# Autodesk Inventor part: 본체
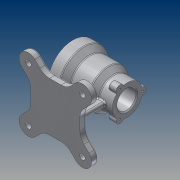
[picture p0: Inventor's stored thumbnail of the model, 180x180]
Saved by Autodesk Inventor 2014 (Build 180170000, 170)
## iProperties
Created: 2017-03
Part Number: 본체
Material: 알루미늄 6061
Document SubType Name: Modeling
Designer: Administrator
Density: 2.71 g/cm^3
Appearance: 알루미늄 - 평지
Mass: 1003.29 g
Surface Area: 840.489 cm^2
Volume: 370.217 cm^3
Author: Administrator
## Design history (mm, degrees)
sketch "스케치1"
  geometry: L1 (-50, 0)-(50, 0); L2 (-50, 45)-(-31.071, 45); L3 (-29.171, 44.322)-(-19.829, 36.678); L4 (-17.929, 36)-(13.929, 36); L5 (15.829, 35.322)-(24.56, 28.178); L6 (26.46, 27.5)-(50, 27.5); L7 (50, 27.5)-(50, 17.5); L8 (50, 17.5)-(23, 17.5); L9 (20, 20.5)-(20, 23); L10 (17, 26)-(-24, 26); L11 (-27, 29)-(-27, 32); L12 (-30, 35)-(-50, 35); L13 (-50, 35)-(-50, 45); A1 r 3 centre (-31.071, 42) between (-29.171, 44.322) and (-31.071, 45); A2 r 3 centre (-17.929, 39) between (-19.829, 36.678) and (-17.929, 36); A3 r 3 centre (13.929, 33) between (15.829, 35.322) and (13.929, 36); A4 r 3 centre (26.46, 30.5) between (24.56, 28.178) and (26.46, 27.5); A5 r 3 centre (-30, 32) between (-27, 32) and (-30, 35); A6 r 3 centre (-24, 29) between (-27, 29) and (-24, 26); A7 r 3 centre (17, 23) between (20, 23) and (17, 26); A8 r 3 centre (23, 20.5) between (20, 20.5) and (23, 17.5); 10 further points
  constraints: 26 end point, 16 point on circle, 16 point on line, 16 tangent, 10 parallel, 8 centre point, 7 equal radius, 2 vertical alignment, 1 coincident, 1 horizontal, 1 midpoint, 1 perpendicular
  dimensions: "d0" = 100 distance of L1.start L1.end; "d1" = 90 diameter of L2 L1; "d2" = 70 diameter of L12 L1; "d3" = 52 diameter of L10 L1; "d4" = 35 diameter of L8 L1; "d5" = 72 diameter of L4 L1; "d6" = 55 diameter of L6 L1; "d7" = 30 distance between parallel lines of L9 L7; "d8" = 23 distance between parallel lines of L11 L13; "d9" = 20 distance from line of point (-30, 45) L13; "d10" = 31 distance from line of point (-19, 36) L13; "d11" = 65 distance from line of L13 point (15, 36); "d13" = 3 radius of A1
revolve "회전1" sketch "스케치1" stored, may be unused: angle "d12" = 90 deg
node "작업 평면1"
sketch "스케치2"
  geometry: L1 (0, 0)-(74.496, 74.496); L2 (0, 0)-(105.353, 0); L3 (61.518, 37.477)-(52.322, 28.281); L4 (37.477, 61.518)-(28.281, 52.322); L5 (37.477, -61.518)-(28.281, -52.322); L6 (61.518, -37.477)-(52.322, -28.281); L7 (0, 0)-(0, 108.585); L8 (-37.477, 61.518)-(-28.281, 52.322); L9 (-61.518, 37.477)-(-52.322, 28.281); L10 (-61.518, -37.477)-(-52.322, -28.281); L11 (-37.477, -61.518)-(-28.281, -52.322); L12 (-10.603, 45)-(10.603, 45); L13 (-45, -10.603)-(-45, 10.603); L14 (10.603, -45)-(-10.603, -45); L15 (45, 10.603)-(45, -10.603); C1 r 5 at (49.497, 49.497); C2 r 5 at (49.497, -49.497); C3 r 5 at (-49.497, 49.497); C4 r 5 at (-49.497, -49.497); A1 r 70 centre (0, 0) between (49.497, 49.497) and (59.97, 36.106); A2 r 17 centre (49.497, 49.497) between (59.97, 36.106) and (36.106, 59.97); A3 r 17 centre (49.497, -49.497) between (36.106, -59.97) and (59.97, -36.106); A4 r 17 centre (-49.497, 49.497) between (-36.106, 59.97) and (-59.97, 36.106); A5 r 17 centre (-49.497, -49.497) between (-59.97, -36.106) and (-36.106, -59.97); A6 r 25 centre (-10.603, 70) between (-28.281, 52.322) and (-10.603, 45); A7 r 25 centre (10.603, 70) between (10.603, 45) and (28.281, 52.322); A8 r 25 centre (70, 10.603) between (52.322, 28.281) and (45, 10.603); A9 r 25 centre (70, -10.603) between (45, -10.603) and (52.322, -28.281); A10 r 25 centre (10.603, -70) between (28.281, -52.322) and (10.603, -45); A11 r 25 centre (-10.603, -70) between (-10.603, -45) and (-28.281, -52.322); A12 r 25 centre (-70, -10.603) between (-52.322, -28.281) and (-45, -10.603); A13 r 25 centre (-70, 10.603) between (-45, 10.603) and (-52.322, 28.281); 10 further points
  constraints: 35 point on circle, 30 end point, 24 symmetric about line, 17 centre point, 17 point on line, 16 tangent, 5 coincident, 5 equal radius, 2 horizontal, 2 midpoint, 2 parallel, 2 perpendicular, 1 equal length, 1 horizontal alignment, 1 vertical alignment, 6 other
  dimensions: "d17" = 45 deg angle of L2 L1; "d18" = 17 distance between parallel lines of L3 L1; "d19" = 17 distance between parallel lines of L4 L1; "d20" = 140 diameter of A1; "d21" = 10 diameter of C1; "d22" = 34 diameter of A2; "d26" = 90 distance between parallel lines of L15 L13; "d27" = 90 distance between parallel lines of L12 L14; "d30" = 25 radius of A6; "d31" = 25 radius of A10; "d32" = 25 radius of A12
extrude "돌출1" join sketch "스케치2" distance "d28" = 12; taper "d29" = 0 deg
sketch "스케치3"
  geometry: L1 (37, 4)-(-37, 4); L2 (-37, 4)-(-37, -4); L3 (-37, -4)-(37, -4); L4 (37, -4)-(37, 4); 3 further points
  constraints: 8 end point, 2 midpoint, 2 parallel, 1 horizontal, 1 horizontal alignment, 1 perpendicular, 1 vertical alignment
  dimensions: "d33" = 8 distance between parallel lines of L3 L1; "d34" = 37 distance from line of point (0, 0) L4
extrude "돌출2" join sketch "스케치3" stored distance "d35" = 12; taper "d36" = 0 deg
sketch "스케치4"
  geometry: L1 (-70, -28.281)-(-70, -37.477) reference; L2 (-70, 37.477)-(-70, 28.281) reference; L3 (-70, 25)-(-31.096, 18.14); L4 (-70, -25)-(-31.096, -18.14); A1 r 36 centre (0, 0) between (-35.777, -4) and (-35.777, 4) reference; 1 further point
  constraints: 4 end point, 2 point on circle, 2 point on line
  dimensions: "d37" = 100 deg angle of L2 L3; "d38" = 100 deg angle of L1 L4; "d39" = 25 vertical distance of L4.start point (0, 0); "d40" = 25 vertical distance of L3.start point (0, 0)
feature "리브1" dims "d41" = 1, "d42" = 8, "d43" = 0, "d44" = 0, "d45" = 1, "d46" = 1
feature "리브2" dims "d47" = 1, "d48" = 8, "d49" = 0, "d50" = 0, "d51" = 1, "d52" = 1
sketch "스케치5"
  geometry: A1 r 27.5 centre (0, 0) between (0, 27.5) and (-6.943, 26.609) reference; A2 r 7 centre (0, 27.5) between (6.943, 26.609) and (-6.943, 26.609); 1 further point
  constraints: 5 point on circle, 1 centre point, 1 vertical alignment
  dimensions: "d53" = 14 diameter of A2
extrude "돌출3" join sketch "스케치5" distance "d54" = 15; taper "d55" = 0 deg
sketch "스케치6"
  geometry: A1 r 7 centre (0, 0) between (6.943, -0.891) and (-6.943, -0.891) reference; 1 further point
hole "구멍1" sketch "스케치6" at (0, 0) diameter "d56" = 3.242; stored, may be unused: countersink angle "d60" = 90 deg, drill point angle "d62" = 118 deg; dims "d57" = 9, "d58" = 4, "d59" = 2, "d61" = 11
node "작업 평면2"
sketch "스케치7"
  geometry: C1 r 5 at (0, 0); 1 further point
  constraints: 1 centre point, 1 coincident
  dimensions: "d67" = 10 diameter of C1
extrude "돌출4" join sketch "스케치7" stored distance "d68" = 15; taper "d69" = 0 deg
hole "구멍2" diameter "d72" = 4.134; stored, may be unused: countersink angle "d76" = 90 deg, drill point angle "d78" = 118 deg; dims "d70" = 10, "d71" = 10, "d73" = 9, "d74" = 4, "d75" = 2, "d77" = 11
chamfer "모따기1" distance "d79" = 2; stored, may be unused: second distance "d80" = 2, angle "d81" = 45 deg
fillet "모깎기3" dims "d84" = 3
fillet "모깎기4" dims "d85" = 1
fillet "모깎기5" dims "d86" = 3
fillet "모깎기6" dims "d87" = 3
fillet "모깎기7" dims "d88" = 3
sketch "스케치8"
  geometry: 2 further points
  constraints: 1 vertical alignment
  dimensions: "d89" = 40 distance of point (0, 0) point (0, 40)
hole "구멍3" sketch "스케치8" at (0, 40) diameter "d90" = 3.242; stored, may be unused: countersink angle "d94" = 90 deg, drill point angle "d96" = 118 deg; dims "d91" = 9, "d92" = 4, "d93" = 2, "d95" = 11
sketch "스케치9"
  geometry: 2 further points
  constraints: 1 vertical alignment, 1 other
  dimensions: "d100" = 35 distance of point (0, -35) point (0, 0)
feature "엠보싱1" sketch "스케치9" dims "d0" = 100, "d1" = 90, "d2" = 70, "d3" = 52, "d4" = 35, "d5" = 72, "d6" = 55, "d7" = 30, "d8" = 23, "d9" = 20, "d10" = 31, "d11" = 65, "d13" = 3, "d101" = 0.5, "d102" = 0
node "솔리드1"
pattern_circular "원형 패턴1" dims angle "d64" = 360 deg
pattern_circular "원형 패턴2" dims angle "d98" = 360 deg
other parameters: "d14" = -82, "d24" = 45, "d25" = 45
